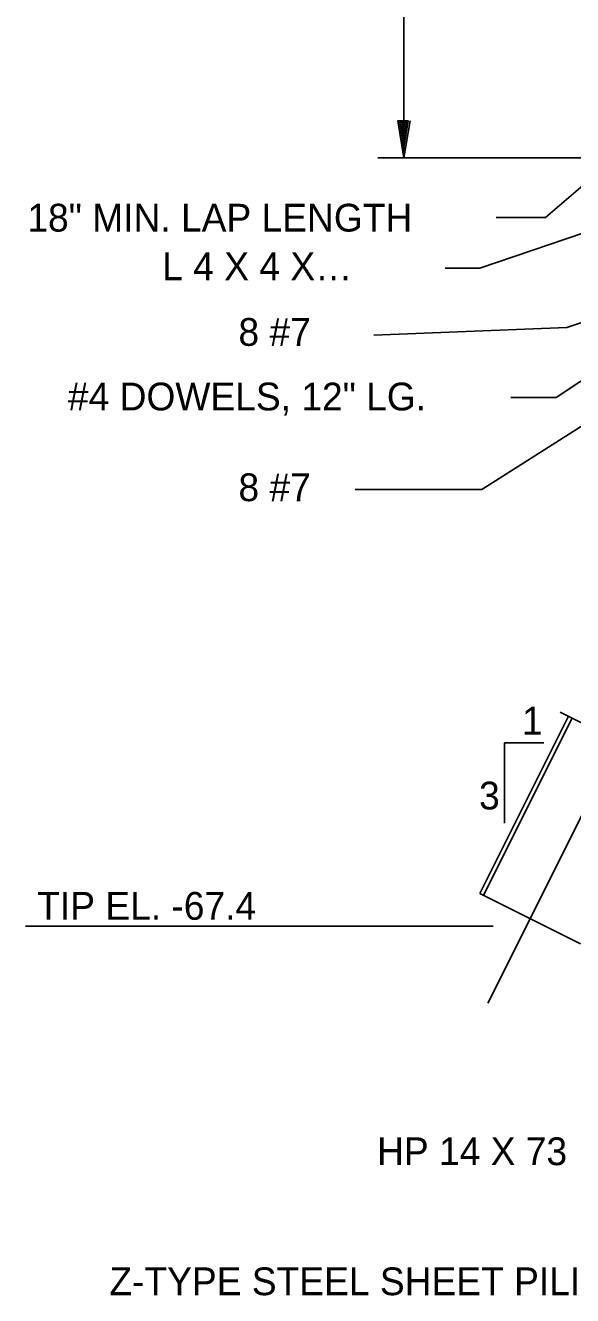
# Model space of a CAD drawing. Extents: x -11983 to -11903, y -13969.5 to -13913.5.
# Drawn here: x -11926.2 to -11920.69, y -13937.66 to -13924.86 of the extents above; entities that cross this region are included whole.
import ezdxf

# ---------------------------------------------------------------- set-up
doc = ezdxf.new("R2010")
doc.units = 0
for name, color, linetype in [('Level 2', 7, 'Continuous'), ('Level 22', 7, 'Continuous'), ('Level 3', 7, 'Continuous'), ('Level 50', 7, 'Continuous')]:
    doc.layers.add(name, color=color, linetype=linetype)

msp = doc.modelspace()

# ---------------------------------------------------------------- linework, layer by layer
at = {"layer": 'Level 2'}
for p, q in [((-11920.336, -13932.019), (-11920.816, -13931.779)), ((-11920.732, -13931.821), (-11921.626, -13933.608)), ((-11920.695, -13931.839), (-11921.589, -13933.626)), ((-11920.611, -13934.116), (-11921.626, -13933.608))]:
    msp.add_line(p, q, dxfattribs=at)
at = {"layer": 'Level 22'}
for p in [(-11920.98, -13932.091), (-11921.375, -13932.9)]:
    msp.add_line(p, (-11921.375, -13932.091), dxfattribs=at)
at = {"layer": 'Level 3'}
for p, q in [((-11922.389, -13926.193), (-11922.389, -13919.919)), ((-11920.962, -13926.792), (-11919.496, -13925.53)), ((-11922.651, -13926.193), (-11916.209, -13926.193)), ((-11921.461, -13926.792), (-11920.962, -13926.792)), ((-11921.626, -13927.303), (-11920.311, -13926.856)), ((-11921.974, -13927.303), (-11921.626, -13927.303)), ((-11919.409, -13927.445), (-11920.747, -13927.902)), ((-11920.747, -13927.902), (-11922.694, -13927.978)), ((-11920.855, -13928.609), (-11919.833, -13927.924)), ((-11919.583, -13928.25), (-11921.605, -13929.534)), ((-11921.312, -13928.609), (-11920.855, -13928.609)), ((-11918.812, -13929.25), (-11921.545, -13934.715)), ((-11922.879, -13929.534), (-11921.605, -13929.534)), ((-11926.203, -13933.938), (-11921.491, -13933.938))]:
    msp.add_line(p, q, dxfattribs=at)
at = {"layer": 'Level 50'}
for p, q in [((-11922.389, -13926.089), (-11922.389, -13926.089)), ((-11922.389, -13926.193), (-11922.389, -13926.193))]:
    msp.add_line(p, q, dxfattribs=at)
msp.add_lwpolyline([(-11922.327, -13925.819), (-11922.389, -13926.193), (-11922.451, -13925.819), (-11922.345, -13925.819), (-11922.389, -13926.089), (-11922.431, -13925.835), (-11922.363, -13925.835), (-11922.389, -13925.989), (-11922.411, -13925.851), (-11922.383, -13925.851), (-11922.389, -13925.885)], dxfattribs=at)

# ---------------------------------------------------------------- texts
at = {"layer": 'Level 3'}
for s, p in [('18" MIN. LAP LENGTH', (-11926.183, -13926.935)), ('L 4 X 4 X…', (-11924.824, -13927.425)), ('8 #7', (-11924.056, -13928.087)), ('#4 DOWELS, 12" LG.', (-11925.774, -13928.738)), ('8 #7', (-11924.056, -13929.653)), ('1', (-11921.2, -13932.006)), ('3', (-11921.632, -13932.761)), ('TIP EL. -67.4 ', (-11926.084, -13933.873)), ('HP 14 X 73', (-11922.66, -13936.347)), ('Z-TYPE STEEL SHEET PILING', (-11925.357, -13937.658))]:
    msp.add_text(s, height=0.28, dxfattribs=at).set_placement(p)

doc.saveas('drawing.dxf')
